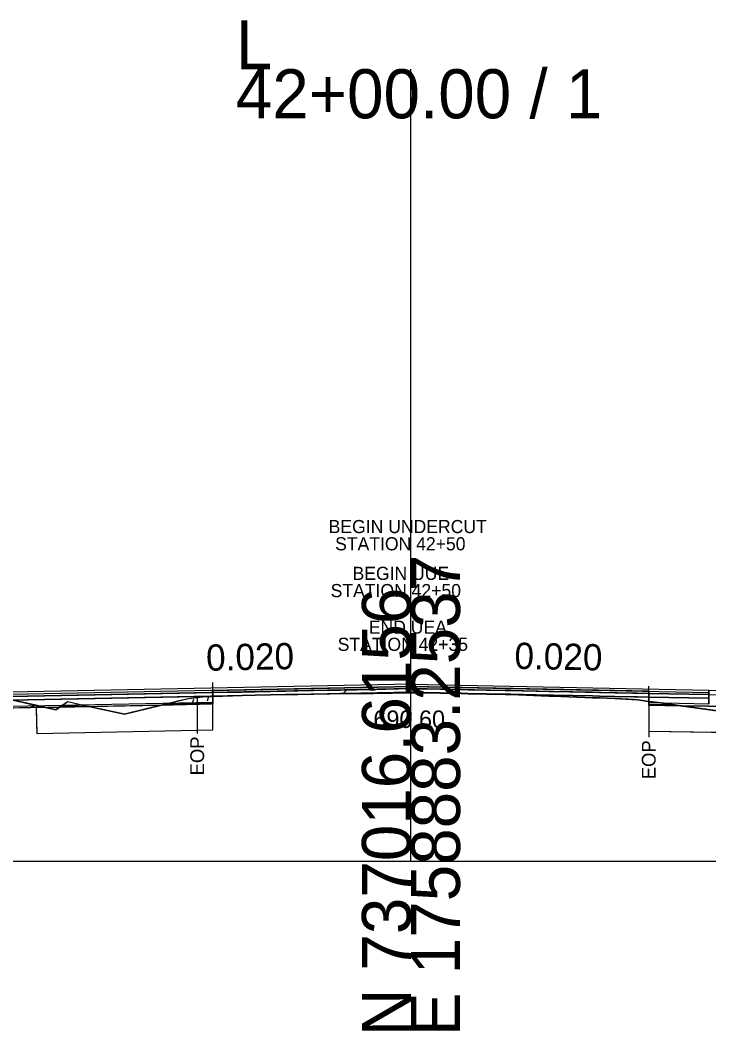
# Model space of a CAD drawing. Extents: x -26 to 4303, y -10 to 9577.
# Drawn here: x 3127.7 to 3167, y 1990.3 to 2048 of the extents above; entities that cross this region are included whole.
import ezdxf

# ---------------------------------------------------------------- set-up
doc = ezdxf.new("R2010")
doc.units = 0
for name, color, linetype in [('Exist CMT Pavement', 7, 'Continuous'), ('Old_Level_2', 7, 'Continuous'), ('Pattern 3', 7, 'Continuous'), ('Prop CMT Conc Surface', 7, 'Continuous'), ('Prop CMT Concrete Structures', 7, 'Continuous'), ('Prop CMT Pvmt Course 1', 7, 'Continuous'), ('Prop CMT Pvmt Course 1 CG', 7, 'Continuous'), ('Prop CMT Pvmt Course 1 Wedge', 7, 'Continuous'), ('Prop CMT Pvmt Course 2', 7, 'Continuous'), ('Prop CMT Pvmt Course 3', 7, 'Continuous'), ('Prop CMT Pvmt Surface', 7, 'Continuous'), ('Prop CMT Pvmt Surface Shoulder', 7, 'Continuous'), ('Prop CMT Pvmt Wedge Surface 1', 7, 'Continuous'), ('Prop CMT Pvmt Wedge Surface 2', 7, 'Continuous'), ('Prop CMT Pvmt Wedge Surface 3', 7, 'Continuous'), ('Prop CMT Shld Paved Course 1', 7, 'Continuous'), ('Prop CMT Shld Paved Course 2', 7, 'Continuous'), ('Prop CMT Shld Paved Course 3', 7, 'Continuous'), ('Prop CMT Slope Grass', 7, 'Continuous'), ('Prop CMT Subgrade Earthwork', 7, 'Continuous'), ('Prop Road Sect_ Recs - UC Shallow (Outline)', 7, 'Continuous'), ('Prop Shade Light', 7, 'Continuous'), ('Prop XS DDE', 7, 'Continuous'), ('Prop XS DDE Elevations', 7, 'Continuous'), ('Prop XS Ditch Standard Text', 7, 'Continuous'), ('Prop XS SE Text', 7, 'Continuous'), ('Prop XS Shear Point Label', 7, 'Continuous'), ('Prop XS Wedging', 7, 'Continuous'), ('Scratch_Level_2', 7, 'Continuous'), ('Scratch_Level_6', 7, 'Continuous'), ('Scratch_Level_9', 7, 'Continuous')]:
    doc.layers.add(name, color=color, linetype=linetype)

msp = doc.modelspace()

# ---------------------------------------------------------------- linework, layer by layer
at = {"layer": 'Exist CMT Pavement'}
for points in [[(3150, 2010.093), (3125.24, 2009.598)], [(3150, 2010.093), (3167, 2009.753)]]:
    msp.add_lwpolyline(points, dxfattribs=at)
at = {"layer": 'Old_Level_2'}
for p, q in [((3150, 2000), (3150, 2045.211)), ((3150, 2000), (3150, 2045.211)), ((3000, 2000), (3150, 2000)), ((3000, 2000), (3150, 2000)), ((3150, 2000), (3300, 2000)), ((3150, 2000), (3300, 2000))]:
    msp.add_line(p, q, dxfattribs=at)
at = {"layer": 'Pattern 3'}
for p, q in [((3128.286, 2008.784), (3128.647, 2008.881)), ((3128.83, 2008.84), (3128.818, 2008.795)), ((3128.987, 2008.805), (3128.994, 2008.798)), ((3130.092, 2008.894), (3130.135, 2008.905))]:
    msp.add_line(p, q, dxfattribs=at)
for points in [[(3121, 2007.553), (3125.717, 2008.733), (3128.607, 2008.791), (3129.015, 2008.799), (3127.892, 2009.049), (3127.155, 2009.213), (3124.901, 2009.715), (3123.731, 2009.974), (3122.243, 2010.258), (3119.837, 2010.719), (3117.781, 2011.112), (3116.358, 2011.212), (3114.859, 2011.451), (3113.78, 2011.623), (3112.64, 2011.804), (3111.747, 2011.891), (3109.852, 2012.063), (3108.901, 2012.389), (3105.839, 2012.037), (3105.261, 2011.971), (3105.02, 2011.943), (3104.701, 2011.929), (3103.679, 2011.884)], [(3129.983, 2008.818), (3130.411, 2009.115), (3131.531, 2008.849)], [(3163.573, 2009.118), (3163.573, 2008.947), (3165.037, 2008.918), (3163.938, 2009.069)]]:
    msp.add_lwpolyline(points, close=True, dxfattribs=at)
msp.add_lwpolyline([(3138.687, 2009.396), (3138.687, 2008.992), (3135.873, 2008.936), (3137.296, 2009.28), (3137.765, 2009.34), (3138.114, 2009.384), (3138.687, 2009.396)], dxfattribs=at)
at = {"layer": 'Prop CMT Conc Surface'}
for points in [[(3138.687, 2009.617), (3125.24, 2009.348)], [(3125.24, 2009.14), (3138.687, 2009.409)], [(3138.687, 2009.409), (3138.687, 2009.617)], [(3163.573, 2009.364), (3163.573, 2009.572)], [(3163.573, 2009.572), (3167, 2009.503)], [(3167, 2009.295), (3163.573, 2009.364)], [(3167, 2009.503), (3167, 2009.295)]]:
    msp.add_lwpolyline(points, dxfattribs=at)
at = {"layer": 'Prop CMT Concrete Structures'}
for points in [[(3150, 2009.968), (3138.687, 2009.742)], [(3150, 2009.968), (3163.573, 2009.697)], [(3138.687, 2009.617), (3125.24, 2009.348)], [(3138.687, 2009.742), (3138.687, 2009.617)], [(3163.573, 2009.697), (3163.573, 2009.572)], [(3163.573, 2009.572), (3167, 2009.503)], [(3167, 2009.503), (3167, 2009.753)]]:
    msp.add_lwpolyline(points, dxfattribs=at)
at = {"layer": 'Prop CMT Pvmt Course 1'}
for points in [[(3138.687, 2009.409), (3125.24, 2009.14)], [(3138.687, 2009.076), (3138.687, 2009.409)], [(3163.573, 2009.364), (3167, 2009.295)], [(3163.573, 2009.03), (3163.573, 2009.364)], [(3167, 2009.295), (3167, 2008.962)], [(3125.24, 2008.807), (3138.687, 2009.076)], [(3167, 2008.962), (3163.573, 2009.03)]]:
    msp.add_lwpolyline(points, dxfattribs=at)
at = {"layer": 'Prop CMT Pvmt Course 1 Wedge'}
for points in [[(3138.687, 2009.409), (3139.581, 2009.427)], [(3139.581, 2009.427), (3138.687, 2009.396)], [(3138.687, 2009.396), (3138.687, 2009.409)], [(3150, 2009.597), (3147.865, 2009.569), (3146.124, 2009.558)], [(3146.124, 2009.558), (3147.865, 2009.592)], [(3147.865, 2009.592), (3150, 2009.635)], [(3150, 2009.635), (3150, 2009.597)], [(3150, 2009.635), (3150.374, 2009.628), (3150.406, 2009.627), (3150.433, 2009.626), (3150.455, 2009.626), (3150.483, 2009.625), (3152.867, 2009.578), (3153.27, 2009.57), (3155.368, 2009.528), (3155.702, 2009.521), (3157.869, 2009.478), (3158.134, 2009.472), (3160.37, 2009.428), (3160.754, 2009.42), (3161.633, 2009.402), (3162.74, 2009.38), (3162.94, 2009.376), (3163.573, 2009.364)], [(3163.573, 2009.118), (3162.94, 2009.203), (3162.74, 2009.216), (3161.633, 2009.285), (3160.754, 2009.312), (3160.37, 2009.321), (3158.134, 2009.405), (3157.869, 2009.415), (3155.702, 2009.505), (3155.368, 2009.515), (3153.27, 2009.551), (3152.867, 2009.562), (3150.483, 2009.601), (3150.455, 2009.602), (3150.433, 2009.602), (3150.406, 2009.602), (3150.374, 2009.602), (3150, 2009.597)], [(3163.573, 2009.364), (3163.573, 2009.118)]]:
    msp.add_lwpolyline(points, dxfattribs=at)
at = {"layer": 'Prop CMT Pvmt Course 2'}
msp.add_lwpolyline([(3167, 2009.503), (3167, 2009.753)], dxfattribs=at)
at = {"layer": 'Prop CMT Pvmt Course 3'}
for points in [[(3167, 2009.503), (3172.046, 2009.403), (3172.258, 2009.19)], [(3167, 2009.295), (3167, 2009.503)]]:
    msp.add_lwpolyline(points, dxfattribs=at)
at = {"layer": 'Prop CMT Pvmt Surface'}
for points in [[(3150, 2009.843), (3125.24, 2009.348)], [(3150, 2009.843), (3167, 2009.503)], [(3167, 2009.503), (3167, 2009.753)]]:
    msp.add_lwpolyline(points, dxfattribs=at)
at = {"layer": 'Prop CMT Pvmt Surface Shoulder'}
for points in [[(3138.688, 2009.396), (3140.362, 2009.454), (3141.111, 2009.471), (3142.863, 2009.504), (3143.543, 2009.516), (3145.364, 2009.55), (3145.975, 2009.557), (3147.865, 2009.569), (3149.998, 2009.597)], [(3149.998, 2009.597), (3150.374, 2009.602), (3150.406, 2009.602), (3150.433, 2009.602), (3150.455, 2009.602), (3150.483, 2009.601), (3152.867, 2009.562), (3153.27, 2009.551), (3155.368, 2009.515), (3155.702, 2009.505), (3157.869, 2009.415), (3158.134, 2009.405), (3160.37, 2009.321), (3160.754, 2009.312), (3161.633, 2009.285), (3162.74, 2009.216), (3162.94, 2009.203), (3163.571, 2009.118)]]:
    msp.add_lwpolyline(points, dxfattribs=at)
at = {"layer": 'Prop CMT Pvmt Wedge Surface 1'}
for p, q in [((3138.686, 2008.95), (3125.258, 2008.682)), ((3163.575, 2008.905), (3166.982, 2008.837)), ((3166.982, 2008.837), (3176.352, 2008.649))]:
    msp.add_line(p, q, dxfattribs=at)
for points in [[(3138.686, 2008.95), (3138.688, 2009.396)], [(3163.575, 2008.905), (3163.571, 2009.118)]]:
    msp.add_lwpolyline(points, dxfattribs=at)
at = {"layer": 'Prop CMT Pvmt Wedge Surface 2'}
for points in [[(3138.687, 2009.742), (3140.362, 2009.776), (3141.111, 2009.791), (3142.863, 2009.826), (3143.543, 2009.839), (3145.364, 2009.876), (3145.975, 2009.888), (3147.865, 2009.926), (3150, 2009.968)], [(3150, 2009.843), (3147.865, 2009.801), (3145.975, 2009.763), (3145.364, 2009.751), (3143.543, 2009.714), (3142.863, 2009.701), (3141.111, 2009.666), (3140.362, 2009.651), (3138.687, 2009.617)], [(3150, 2009.968), (3150, 2009.843)], [(3150, 2009.968), (3150.374, 2009.961), (3150.406, 2009.96), (3150.433, 2009.96), (3150.455, 2009.959), (3150.483, 2009.959), (3152.867, 2009.911), (3153.27, 2009.903), (3155.368, 2009.861), (3155.702, 2009.854), (3157.869, 2009.811), (3158.134, 2009.806), (3160.37, 2009.761), (3160.754, 2009.753), (3161.633, 2009.736), (3162.74, 2009.714), (3162.94, 2009.71), (3163.573, 2009.697)], [(3163.573, 2009.572), (3162.94, 2009.585), (3162.74, 2009.589), (3161.633, 2009.611), (3160.754, 2009.628), (3160.37, 2009.636), (3158.134, 2009.681), (3157.869, 2009.686), (3155.702, 2009.729), (3155.368, 2009.736), (3153.27, 2009.778), (3152.867, 2009.786), (3150.483, 2009.834), (3150.455, 2009.834), (3150.433, 2009.835), (3150.406, 2009.835), (3150.374, 2009.836), (3150, 2009.843)], [(3138.687, 2009.617), (3138.687, 2009.742)], [(3163.573, 2009.697), (3163.573, 2009.572)]]:
    msp.add_lwpolyline(points, dxfattribs=at)
at = {"layer": 'Prop CMT Pvmt Wedge Surface 3'}
for points in [[(3138.687, 2009.617), (3140.362, 2009.651), (3141.111, 2009.666), (3142.863, 2009.701), (3143.543, 2009.714), (3145.364, 2009.751), (3145.975, 2009.763), (3147.865, 2009.801), (3150, 2009.843)], [(3150, 2009.843), (3150, 2009.635)], [(3150, 2009.843), (3150.374, 2009.836), (3150.406, 2009.835), (3150.433, 2009.835), (3150.455, 2009.834), (3150.483, 2009.834), (3152.867, 2009.786), (3153.27, 2009.778), (3155.368, 2009.736), (3155.702, 2009.729), (3157.869, 2009.686), (3158.134, 2009.681), (3160.37, 2009.636), (3160.754, 2009.628), (3161.633, 2009.611), (3162.74, 2009.589), (3162.94, 2009.585), (3163.573, 2009.572)], [(3150, 2009.635), (3147.865, 2009.592), (3146.124, 2009.558), (3145.975, 2009.557), (3145.364, 2009.55), (3143.543, 2009.516), (3142.863, 2009.504), (3141.111, 2009.471), (3140.362, 2009.454), (3139.581, 2009.427), (3138.687, 2009.409)], [(3138.687, 2009.409), (3138.687, 2009.617)], [(3163.573, 2009.364), (3162.94, 2009.376), (3162.74, 2009.38), (3161.633, 2009.402), (3160.754, 2009.42), (3160.37, 2009.428), (3158.134, 2009.472), (3157.869, 2009.478), (3155.702, 2009.521), (3155.368, 2009.528), (3153.27, 2009.57), (3152.867, 2009.578), (3150.483, 2009.625), (3150.455, 2009.626), (3150.433, 2009.626), (3150.406, 2009.627), (3150.374, 2009.628), (3150, 2009.635)], [(3163.573, 2009.572), (3163.573, 2009.364)]]:
    msp.add_lwpolyline(points, dxfattribs=at)
at = {"layer": 'Prop CMT Shld Paved Course 1'}
for points in [[(3150, 2009.635), (3125.24, 2009.14)], [(3150, 2009.635), (3167, 2009.295)], [(3167, 2009.295), (3167, 2009.753)]]:
    msp.add_lwpolyline(points, dxfattribs=at)
at = {"layer": 'Prop CMT Shld Paved Course 2'}
msp.add_lwpolyline([(3167, 2009.753), (3169, 2009.713)], dxfattribs=at)
at = {"layer": 'Prop CMT Shld Paved Course 3'}
for points in [[(3150, 2010.093), (3125.24, 2009.598)], [(3138.687, 2009.742), (3150, 2009.968)], [(3150, 2009.843), (3150, 2010.093)], [(3150, 2010.093), (3167, 2009.753)], [(3150, 2009.968), (3150, 2009.843), (3150, 2009.843)], [(3163.573, 2009.697), (3150, 2009.968)], [(3125.24, 2009.348), (3138.687, 2009.617)], [(3138.687, 2009.617), (3138.687, 2009.742)], [(3163.573, 2009.572), (3163.573, 2009.697)], [(3167, 2009.503), (3163.573, 2009.572)], [(3167, 2009.753), (3167, 2009.503)]]:
    msp.add_lwpolyline(points, dxfattribs=at)
at = {"layer": 'Prop CMT Slope Grass'}
msp.add_lwpolyline([(3123.805, 2009.959), (3129.726, 2008.64), (3130.411, 2009.115), (3131.456, 2008.865), (3133.647, 2008.382), (3136.774, 2009.16), (3137.296, 2009.28), (3138.114, 2009.384), (3138.679, 2009.395), (3140.362, 2009.454), (3141.111, 2009.471), (3142.863, 2009.504), (3143.543, 2009.516), (3145.364, 2009.55), (3145.975, 2009.557), (3147.865, 2009.569), (3150, 2009.597), (3150.433, 2009.602), (3152.867, 2009.562), (3153.27, 2009.551), (3155.368, 2009.515), (3155.702, 2009.505), (3158.134, 2009.405), (3160.37, 2009.321), (3160.754, 2009.312), (3161.633, 2009.285), (3162.94, 2009.203), (3164.11, 2009.045), (3170.399, 2008.178)], dxfattribs=at)
at = {"layer": 'Prop CMT Subgrade Earthwork'}
msp.add_lwpolyline([(3167, 2008.962), (3167, 2009.295)], dxfattribs=at)
at = {"layer": 'Prop Road Sect_ Recs - UC Shallow (Outline)'}
msp.add_line((3163.573, 2007.42), (3171.278, 2007.293), dxfattribs=at)
for points in [[(3128.607, 2008.791), (3128.637, 2007.291), (3138.687, 2007.492), (3138.687, 2008.992), (3135.89, 2008.94), (3133.647, 2008.382), (3131.531, 2008.849), (3129.983, 2008.818), (3129.726, 2008.64), (3129.007, 2008.801)], [(3163.573, 2007.42), (3171.278, 2007.293), (3171.278, 2008.165), (3170.399, 2008.178), (3165.037, 2008.918), (3163.573, 2008.92)]]:
    msp.add_lwpolyline(points, close=True, dxfattribs=at)
at = {"layer": 'Prop Shade Light'}
for p, q in [((3129.007, 2008.801), (3128.607, 2008.791)), ((3128.607, 2008.791), (3128.626, 2007.824)), ((3129.726, 2008.64), (3129.007, 2008.801)), ((3129.983, 2008.818), (3129.726, 2008.64)), ((3130.687, 2008.832), (3129.983, 2008.818)), ((3131.531, 2008.849), (3130.687, 2008.832)), ((3133.647, 2008.382), (3131.531, 2008.849)), ((3135.89, 2008.94), (3133.647, 2008.382)), ((3138.688, 2008.992), (3135.89, 2008.94)), ((3138.687, 2007.492), (3138.688, 2008.992)), ((3163.573, 2008.947), (3163.573, 2007.42)), ((3165.001, 2008.923), (3163.573, 2008.947)), ((3170.399, 2008.178), (3165.001, 2008.923)), ((3128.626, 2007.824), (3128.637, 2007.291)), ((3128.637, 2007.291), (3138.687, 2007.492)), ((3163.573, 2007.42), (3171.278, 2007.293))]:
    msp.add_line(p, q, dxfattribs=at)
at = {"layer": 'Prop XS DDE Elevations'}
for points in [[(3125.258, 2008.682), (3123.258, 2008.642), (3120.2, 2009.138), (3121.24, 2009.398), (3123.24, 2009.558), (3125.24, 2009.598), (3125.41, 2009.602), (3129.187, 2008.76)], [(3137.296, 2009.28), (3138.114, 2009.384), (3138.688, 2009.396), (3138.686, 2008.95), (3135.69, 2008.89), (3136.774, 2009.16)], [(3150.374, 2009.602), (3150.406, 2009.602), (3150.433, 2009.602), (3149.998, 2009.597)], [(3157.869, 2009.415), (3158.134, 2009.405), (3155.702, 2009.505)], [(3161.633, 2009.285), (3162.74, 2009.216), (3162.94, 2009.203)], [(3129.726, 2008.64), (3129.92, 2008.775), (3129.187, 2008.76)], [(3131.456, 2008.865), (3131.703, 2008.811), (3129.92, 2008.775), (3130.411, 2009.115)], [(3135.69, 2008.89), (3131.703, 2008.811), (3133.647, 2008.382)], [(3163.575, 2008.905), (3165.391, 2008.869), (3164.11, 2009.045), (3163.571, 2009.118)], [(3177.285, 2008.078), (3177.909, 2008.131), (3176.352, 2008.649), (3166.982, 2008.837), (3165.391, 2008.869), (3170.399, 2008.178)]]:
    msp.add_lwpolyline(points, close=True, dxfattribs=at)
at = {"layer": 'Prop XS Ditch Standard Text'}
for p, q in [((3137.797, 2009.339), (3137.797, 2007.289)), ((3163.573, 2009.118), (3163.573, 2007.067))]:
    msp.add_line(p, q, dxfattribs=at)
at = {"layer": 'Prop XS Wedging'}
for p, q in [((3138.688, 2009.396), (3138.688, 2010.194)), ((3146.333, 2009.77), (3149.995, 2009.843)), ((3149.995, 2009.843), (3150, 2009.843)), ((3150, 2009.843), (3150.005, 2009.843)), ((3150.005, 2009.843), (3150, 2009.843)), ((3150.005, 2009.843), (3163.572, 2009.572)), ((3163.572, 2009.572), (3150.005, 2009.843)), ((3163.573, 2009.118), (3163.573, 2009.985)), ((3138.688, 2009.742), (3138.688, 2009.396)), ((3138.688, 2009.396), (3140.362, 2009.454)), ((3140.362, 2009.454), (3141.111, 2009.471)), ((3146.333, 2009.77), (3146.129, 2009.558)), ((3146.129, 2009.558), (3146.333, 2009.77)), ((3146.333, 2009.77), (3146.129, 2009.558)), ((3146.129, 2009.558), (3147.865, 2009.569)), ((3147.865, 2009.569), (3149.998, 2009.597)), ((3158.134, 2009.405), (3160.37, 2009.321)), ((3160.37, 2009.321), (3160.754, 2009.312)), ((3163.571, 2009.118), (3163.572, 2009.572)), ((3163.572, 2009.572), (3163.572, 2009.697)), ((3162.94, 2009.203), (3163.571, 2009.118))]:
    msp.add_line(p, q, dxfattribs=at)
for points in [[(3150.002, 2009.968), (3125.242, 2009.473)], [(3150, 2009.968), (3149.998, 2009.968), (3138.688, 2009.742)], [(3150.005, 2009.843), (3146.333, 2009.77)], [(3150, 2009.843), (3149.995, 2009.843), (3146.333, 2009.77)], [(3149.995, 2009.843), (3166.995, 2009.503)], [(3149.995, 2009.843), (3149.995, 2009.843)], [(3149.998, 2009.968), (3166.998, 2009.628)], [(3163.572, 2009.697), (3150.002, 2009.968), (3150, 2009.968)], [(3150.005, 2009.843), (3150.005, 2009.843)], [(3141.111, 2009.471), (3142.863, 2009.504), (3143.543, 2009.516), (3145.364, 2009.55)], [(3145.364, 2009.55), (3145.975, 2009.557), (3146.129, 2009.558)], [(3149.998, 2009.597), (3150.374, 2009.602), (3150.406, 2009.602), (3150.433, 2009.602), (3150.455, 2009.602), (3150.483, 2009.601), (3152.867, 2009.562), (3153.27, 2009.551), (3155.368, 2009.515), (3155.702, 2009.505)], [(3155.702, 2009.505), (3157.869, 2009.416), (3158.134, 2009.405)], [(3160.754, 2009.312), (3161.633, 2009.285), (3162.74, 2009.216), (3162.94, 2009.203)]]:
    msp.add_lwpolyline(points, dxfattribs=at)
at = {"layer": 'Scratch_Level_2'}
for p, q in [((3138.446, 2009.396), (3138.374, 2009.129)), ((3130.387, 2009.098), (3130.431, 2009.11)), ((3136.975, 2009.056), (3136.989, 2009.042)), ((3137.579, 2009.218), (3137.534, 2009.053))]:
    msp.add_line(p, q, dxfattribs=at)
at = {"layer": 'Scratch_Level_9'}
msp.add_line((3130.843, 2008.933), (3130.857, 2008.919), dxfattribs=at)

# ---------------------------------------------------------------- texts
at = {"layer": 'Old_Level_2'}
for s, p in [('L', (3140, 2045.211)), ('L', (3140, 2045.211)), ('42+00.00 / 1', (3140, 2042.411)), ('42+00.00 / 1', (3140, 2042.411))]:
    msp.add_text(s, height=2.8, dxfattribs=at).set_placement(p)
for s, p in [('E 1758883.2537', (3152.8, 1990)), ('E 1758883.2537', (3152.8, 1990)), ('N 737016.6156', (3150, 1990)), ('N 737016.6156', (3150, 1990))]:
    msp.add_text(s, height=2.8, rotation=90, dxfattribs=at).set_placement(p)
at = {"layer": 'Prop CMT Pvmt Course 1 CG'}
msp.add_text('690.60', height=1, dxfattribs=at).set_placement((3147.855, 2007.597))
at = {"layer": 'Prop XS DDE'}
for s, p in [('END UEA', (3147.592, 2012.984)), ('STATION 42+35', (3145.815, 2012.001))]:
    msp.add_text(s, height=0.75, dxfattribs=at).set_placement(p)
at = {"layer": 'Prop XS Ditch Standard Text'}
for p in [(3138.191, 2004.89), (3163.966, 2004.669)]:
    msp.add_text('EOP', height=0.7874, rotation=90, dxfattribs=at).set_placement(p)
at = {"layer": 'Prop XS SE Text'}
for rotation, p in [(1.14576, (3138.32, 2010.86)), (358.85424, (3155.896, 2010.976))]:
    msp.add_text('0.020', height=1.5, rotation=rotation, dxfattribs=at).set_placement(p)
at = {"layer": 'Prop XS Shear Point Label'}
for s, p in [('BEGIN UNDERCUT', (3145.302, 2018.723)), ('STATION 42+50', (3145.671, 2017.74))]:
    msp.add_text(s, height=0.75, dxfattribs=at).set_placement(p)
at = {"layer": 'Scratch_Level_6'}
for s, p in [('BEGIN UUE', (3146.665, 2016.051)), ('STATION 42+50', (3145.414, 2015.068))]:
    msp.add_text(s, height=0.75, dxfattribs=at).set_placement(p)

doc.saveas('drawing.dxf')
